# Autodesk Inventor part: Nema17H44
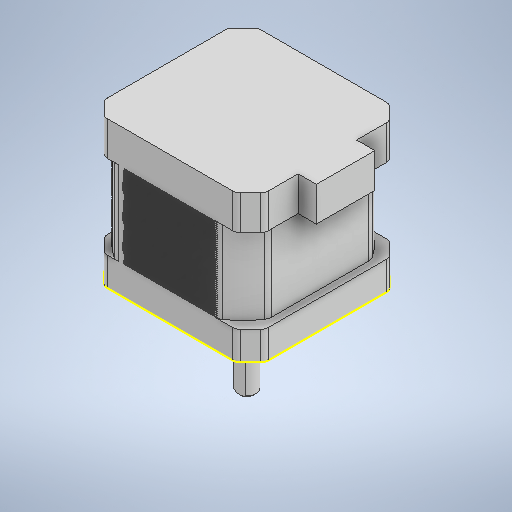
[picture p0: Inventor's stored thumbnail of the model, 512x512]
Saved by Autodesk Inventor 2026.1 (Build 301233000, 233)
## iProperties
Created: 2025-12
Part Number: Nema17H44
Material: Типовые
Document SubType Name: Modeling
Designer: Yury Melnikov
Density: 1 g/cm^3
Appearance: По умолчанию
Author: Yury Melnikov
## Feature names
1. Выдавливание1 [Extrusion]
2. Выдавливание2 [Extrusion]
3. Выдавливание3 [Extrusion]
4. Сопряжение2 [Fillet]
5. Сдвиг1
6. Круговой массив1 [Circular Pattern]
7. Выдавливание4 [Extrusion]
8. Сопряжение3 [Fillet]
9. Выдавливание5 [Extrusion]
10. Фаска2 [Chamfer]
11. Выдавливание6 [Extrusion]
12. Выдавливание7 [Extrusion]
13. Выдавливание8 [Extrusion]
14. Фаска3 [Chamfer]
15. Выдавливание13 [Extrusion]
16. Выдавливание14 [Extrusion]
17. Выдавливание15 [Extrusion]
18. Выдавливание16 [Extrusion]
19. Выдавливание17 [Extrusion]
20. Сопряжение4 [Fillet]
21. Выдавливание18 [Extrusion]
22. Выдавливание19 [Extrusion]
23. Фаска6 [Chamfer]
24. Сопряжение5 [Fillet]
25. Выдавливание20 [Extrusion]
26. Выдавливание23 [Extrusion]
27. Зеркальное отражение2 [Mirror]
28. Выдавливание24 [Extrusion]
29. Выдавливание25 [Extrusion]
## Parameters: d0 = 44 mm, d1 = 42 mm, d2 = 4 mm, d3 = 4 mm, d4 = 4 mm, d5 = 4 mm, d6 = 4 mm, d7 = 4 mm, d8 = 4 mm, d9 = 4 mm, d10 = 2 mm, d11 = 9.4 mm, d12 = 0, d14 = 42 mm, d15 = 7 mm, d16 = 7 mm, d17 = 7 mm, d18 = 7 mm, d19 = 7 mm, d20 = 7 mm, d21 = 7 mm, d22 = 7 mm, d26 = 360 deg, d28 = 22.9 mm, d29 = 0, d30 = 7.8 mm, d31 = 0, d32 = 3 mm, d35 = 0.229 mm, d38 = 0.458 mm, d43 = -11.5 mm, d44 = -15.75 mm, d45 = 0, d46 = 0, d48 = 360 deg, d50 = 22 mm, d51 = 1.9 mm, d52 = 0, d53 = 1 mm, d54 = 9 mm, d55 = 5 mm, d57 = 26.3 mm, d58 = 0, d62 = 0.6 mm, d63 = 2 mm, d64 = 45 deg, d65 = 4.4 mm, d66 = 22.1 mm, d67 = 0, d68 = 5 mm, d69 = 16 mm, d70 = 22.1 mm, d71 = 0, d74 = 30.5 mm, d77 = 30.5 mm, d80 = 2.6 mm, d82 = 0, d83 = 0.6 mm, d84 = 2 mm, d85 = 45 deg, d101 = 3 mm, d102 = 3 mm, d103 = 0, d105 = 0.4 mm, d106 = 3 mm, d107 = 0, d108 = 7 mm, d109 = 37.25 mm, d110 = 0, d113 = 3 mm, d114 = 0, d116 = 0, d117 = 4 mm, d118 = 3 mm, d119 = 3 mm, d120 = 1.75 mm, d123 = 30.5 mm, d126 = 30.5 mm, d130 = 0, d132 = 8 mm, d133 = 4 mm, d134 = 23 mm, d136 = 0, d143 = 12 mm, d144 = 3.2 mm, d145 = 8 mm, d146 = 2 mm, d147 = 45 deg, d148 = 5 mm, d149 = 16.227 mm, d150 = 4.625 mm, d152 = 0, d159 = 3 mm, d161 = 3 mm, d162 = 232 mm, d163 = 4 mm, d164 = 0, d165 = 45 deg, d166 = 3 mm, d167 = 3 mm, d168 = 2 mm, d169 = 0, d170 = 1 mm, d171 = 0
